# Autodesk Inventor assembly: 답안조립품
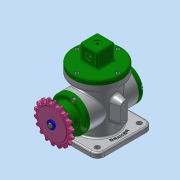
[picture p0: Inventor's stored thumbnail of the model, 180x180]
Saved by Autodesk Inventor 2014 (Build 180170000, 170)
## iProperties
Created: 2021-03
Part Number: 답안조립품
Document SubType Name: Assembly
Designer: net
Author: net
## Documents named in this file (18)
- C:\Users\net\Desktop\710306V1021\답안조립품.iam
- C:\Users\net\Desktop\710306V1021\본체.ipt
- C:\Users\net\Desktop\710306V1021\편심축.ipt
- C:\Users\net\Desktop\710306V1021\베어링 17 x 40 x 12.ipt
- C:\Users\net\Desktop\710306V1021\링크.ipt
- C:\Users\net\Desktop\710306V1021\슬라이더.ipt
- C:\Users\net\Desktop\710306V1021\클레비스 핀 6 x 22.ipt
- 클레비스 핀 6 x 22.ipt
- C:\Users\net\Desktop\710306V1021\E-링.ipt
- C:\Users\net\Desktop\710306V1021\앞커버.ipt
- C:\Users\net\Desktop\710306V1021\뒤커버.ipt
- C:\Users\net\Desktop\710306V1021\오일 실 17 30 8.ipt
- C:\Users\net\Desktop\710306V1021\키 4 x 4 x 12.ipt
- C:\Users\net\Desktop\710306V1021\스프로킷.ipt
- C:\Users\net\Desktop\710306V1021\와셔 4x16.ipt
- C:\Users\net\Desktop\710306V1021\볼트 M4 x 8.ipt
- C:\Users\net\Desktop\710306V1021\덮개.ipt
- C:\Users\net\Desktop\710306V1021\볼트 M4 x 10.ipt
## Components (1 placed, 1 different names)
1. E-링:1
